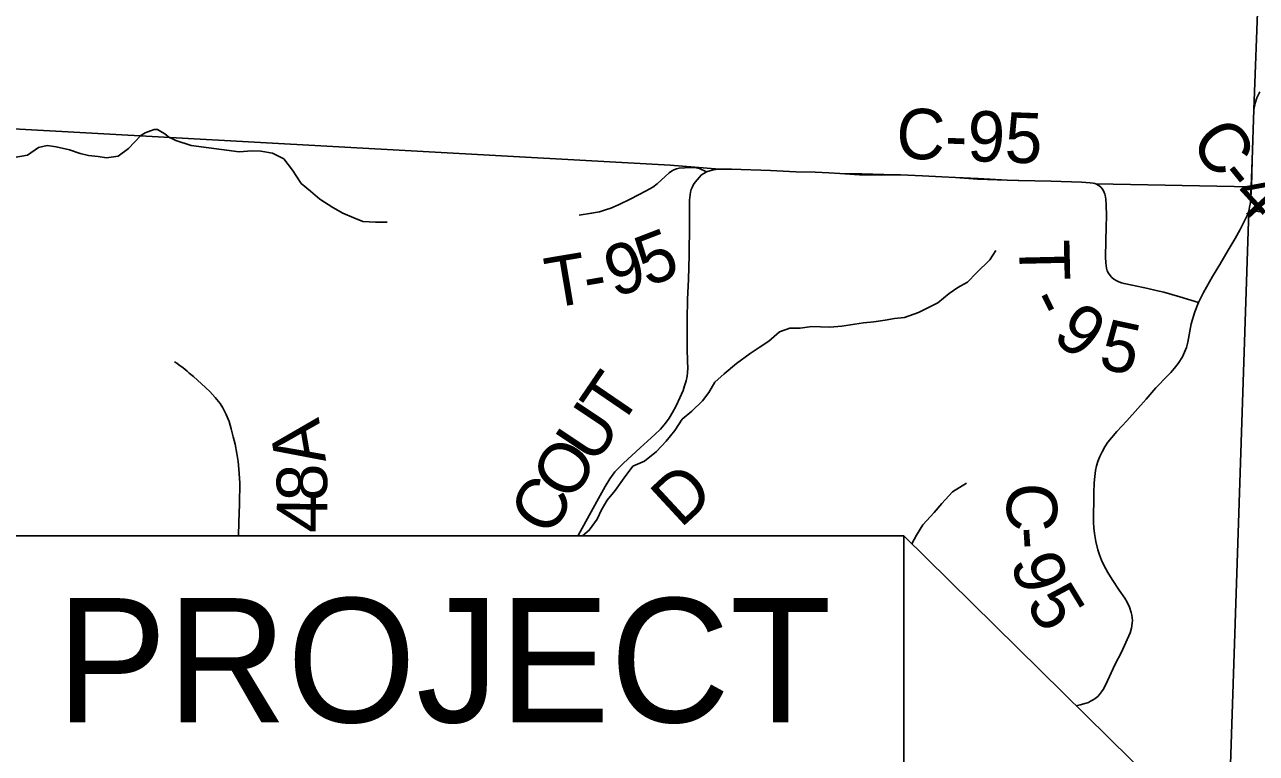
# Model space of a CAD drawing. Extents: x 0 to 34, y 0 to 22.
# Drawn here: x 24.872 to 26.261, y 17.319 to 18.14 of the extents above; entities that cross this region are included whole.
import ezdxf

# ---------------------------------------------------------------- set-up
doc = ezdxf.new("R2010")
doc.units = 0
for name, color, linetype in [('GM_X_Adjacent_County', 7, 'Continuous'), ('GM_X_County', 7, 'Continuous'), ('GM_X_County_Road', 7, 'Continuous'), ('GM_X_County_Road_Text', 7, 'Continuous'), ('GM_X_Minor_River', 7, 'Continuous'), ('GM_X_Township', 7, 'Continuous'), ('GM_X_Township_Road', 7, 'Continuous'), ('GM_X_Township_Road_Text', 7, 'Continuous'), ('SH_Text', 7, 'Continuous')]:
    doc.layers.add(name, color=color, linetype=linetype)

msp = doc.modelspace()

# ---------------------------------------------------------------- linework, layer by layer
at = {"layer": 'GM_X_Adjacent_County'}
for points in [[(26.3979, 17.9244), (26.2521, 17.9299), (26.2531, 17.9341), (26.254, 17.9396), (26.2553, 17.9572), (26.0796, 17.9606), (26.0785, 17.961), (26.0767, 17.9614), (26.0733, 17.9618), (26.0637, 17.9623), (26.0295, 17.9634), (26.0109, 17.964), (25.9929, 17.9644), (25.9923, 17.9644), (25.9799, 17.9648), (25.947, 17.9664), (25.9215, 17.9676), (25.906, 17.9685), (25.8843, 17.9696), (25.8594, 17.9705), (25.8408, 17.971), (25.816, 17.9716), (25.7912, 17.9723), (25.7788, 17.9729), (25.7632, 17.9735), (25.7416, 17.9742), (25.713, 17.9754), (25.6692, 17.9772), (25.6557, 17.9772), (25.5999, 17.9814), (24.5675, 18.0386)], [(24.5675, 18.0386), (25.5999, 17.9814), (25.6557, 17.9772), (25.6692, 17.9772), (25.713, 17.9754), (25.7416, 17.9742), (25.7632, 17.9735), (25.7788, 17.9729), (25.7912, 17.9723), (25.816, 17.9716), (25.8408, 17.971), (25.8594, 17.9705), (25.8843, 17.9696), (25.906, 17.9685), (25.9215, 17.9676), (25.947, 17.9664), (25.9799, 17.9648), (25.9923, 17.9644), (25.9929, 17.9644), (26.0109, 17.964), (26.0295, 17.9634), (26.0637, 17.9623), (26.0733, 17.9618), (26.0767, 17.9614), (26.0785, 17.961), (26.0796, 17.9606), (26.2553, 17.9572), (26.254, 17.9396), (26.2531, 17.9341), (26.2521, 17.9299), (26.3979, 17.9244)]]:
    msp.add_lwpolyline(points, dxfattribs=at)
at = {"layer": 'GM_X_County'}
for points in [[(24.5675, 18.0386), (25.5999, 17.9814), (25.6557, 17.9772), (25.6692, 17.9772), (25.713, 17.9754), (25.7416, 17.9742), (25.7632, 17.9735), (25.7788, 17.9729), (25.7912, 17.9723), (25.816, 17.9716), (25.8408, 17.971), (25.8594, 17.9705), (25.8843, 17.9696), (25.906, 17.9685), (25.9215, 17.9676), (25.947, 17.9664), (25.9799, 17.9648), (25.9923, 17.9644), (25.9929, 17.9644), (26.0109, 17.964), (26.0295, 17.9634), (26.0637, 17.9623), (26.0733, 17.9618), (26.0767, 17.9614), (26.0785, 17.961), (26.0796, 17.9606), (26.2553, 17.9572), (26.254, 17.9396), (26.2531, 17.9341), (26.2521, 17.9299), (26.3979, 17.9244)], [(26.3979, 17.9244), (26.2521, 17.9299), (26.2531, 17.9341), (26.254, 17.9396), (26.2553, 17.9572), (26.0796, 17.9606), (26.0785, 17.961), (26.0767, 17.9614), (26.0733, 17.9618), (26.0637, 17.9623), (26.0295, 17.9634), (26.0109, 17.964), (25.9929, 17.9644), (25.9923, 17.9644), (25.9799, 17.9648), (25.947, 17.9664), (25.9215, 17.9676), (25.906, 17.9685), (25.8843, 17.9696), (25.8594, 17.9705), (25.8408, 17.971), (25.816, 17.9716), (25.7912, 17.9723), (25.7788, 17.9729), (25.7632, 17.9735), (25.7416, 17.9742), (25.713, 17.9754), (25.6692, 17.9772), (25.6557, 17.9772), (25.5999, 17.9814), (24.5675, 18.0386)]]:
    msp.add_lwpolyline(points, dxfattribs=at)
at = {"layer": 'GM_X_County_Road'}
for points in [[(26.2547, 17.9571), (26.2561, 17.9871), (26.2579, 18.0444), (26.2593, 18.0513), (26.2611, 18.0574), (26.2645, 18.0641)], [(25.4958, 17.5637), (25.4966, 17.5651), (25.5191, 17.6059), (25.5268, 17.6195), (25.5319, 17.6282), (25.5375, 17.6358), (25.5473, 17.6459), (25.5662, 17.6631), (25.5825, 17.6782), (25.589, 17.6842), (25.5948, 17.6908), (25.5987, 17.6964), (25.6027, 17.7029), (25.6067, 17.7102), (25.6107, 17.7194), (25.6144, 17.7277), (25.6162, 17.7328), (25.618, 17.7387), (25.6192, 17.7439), (25.6196, 17.7475), (25.6198, 17.7532), (25.6196, 17.7603), (25.619, 17.7751), (25.6189, 17.7888), (25.619, 17.8074), (25.6196, 17.8304), (25.6204, 17.8528), (25.6212, 17.8801), (25.6216, 17.9142), (25.6216, 17.9297), (25.6217, 17.9421), (25.6223, 17.9483), (25.6229, 17.9513), (25.6237, 17.9543), (25.6249, 17.9571), (25.6264, 17.9598), (25.6281, 17.9624), (25.6326, 17.9678), (25.6352, 17.9705), (25.6377, 17.9722), (25.6408, 17.9739)], [(26.0796, 17.9606), (26.0785, 17.961), (26.0767, 17.9614), (26.0733, 17.9618), (26.0637, 17.9623), (26.0295, 17.9634), (26.0109, 17.964), (25.9929, 17.9644), (25.9923, 17.9644), (25.9799, 17.9648), (25.9465, 17.9657), (25.9215, 17.9676), (25.906, 17.9685), (25.8843, 17.9696), (25.8594, 17.9705), (25.838, 17.9702), (25.8132, 17.9705), (25.7912, 17.9723), (25.7788, 17.9729), (25.7632, 17.9735), (25.7416, 17.9742), (25.713, 17.9754), (25.6692, 17.9772), (25.6557, 17.9772)], [(26.2521, 17.9299), (26.2531, 17.9341), (26.254, 17.9396), (26.2541, 17.9426), (26.2547, 17.9571)], [(26.0575, 17.3724), (26.0622, 17.3733), (26.0689, 17.3753), (26.0716, 17.3762), (26.0738, 17.3774), (26.0767, 17.3792), (26.0791, 17.3806), (26.0818, 17.3827), (26.0838, 17.3851), (26.0862, 17.3879), (26.0881, 17.3907), (26.0906, 17.3955), (26.1015, 17.4192), (26.1086, 17.4329), (26.1183, 17.4545), (26.1199, 17.46), (26.1208, 17.4655), (26.1209, 17.4686), (26.1207, 17.4716), (26.1202, 17.4746), (26.1195, 17.4776), (26.1175, 17.4834), (26.115, 17.4891), (26.1125, 17.4936), (26.1062, 17.5026), (26.0981, 17.5146), (26.0931, 17.5226), (26.0887, 17.5308), (26.086, 17.5365), (26.0837, 17.5423), (26.0818, 17.5482), (26.0796, 17.5573), (26.0781, 17.5666), (26.0775, 17.5728), (26.0772, 17.579), (26.0775, 17.6122), (26.078, 17.6237), (26.0785, 17.6306), (26.0793, 17.6375), (26.0804, 17.6426), (26.0819, 17.6475), (26.0843, 17.6531), (26.0867, 17.6585), (26.09, 17.6643), (26.0934, 17.6695), (26.0972, 17.6744), (26.1035, 17.6816), (26.1146, 17.6936), (26.1364, 17.7179), (26.1473, 17.7305), (26.161, 17.7446), (26.1643, 17.7481), (26.168, 17.7526), (26.1725, 17.758), (26.1774, 17.7657), (26.1808, 17.7734), (26.1819, 17.7762), (26.1835, 17.7821), (26.187, 17.8029), (26.1913, 17.8163), (26.1953, 17.8269)]]:
    msp.add_lwpolyline(points, dxfattribs=at)
at = {"layer": 'GM_X_Minor_River'}
for points in [[(24.9961, 18.0075), (25.0034, 18.0151), (25.0083, 18.0181), (25.014, 18.0204), (25.0182, 18.0216), (25.022, 18.0216), (25.0258, 18.0193), (25.0303, 18.0167), (25.0349, 18.0132), (25.039, 18.0114), (25.0428, 18.0095), (25.0601, 18.0038)], [(24.8603, 17.9902), (24.8755, 17.9929), (24.8879, 18.0013), (24.8978, 18.0036), (24.908, 18.0021), (24.9228, 17.9988), (24.9349, 17.9946), (24.9444, 17.9924), (24.955, 17.9913), (24.9644, 17.9898), (24.9777, 17.9917), (24.9892, 18.0004), (24.9961, 18.0075)], [(25.0601, 18.0038), (25.114, 17.9964), (25.1283, 17.9976), (25.1386, 17.9972), (25.1518, 17.995), (25.1643, 17.9886), (25.1742, 17.9761), (25.1841, 17.9609), (25.1944, 17.9523), (25.205, 17.9432), (25.2198, 17.9338), (25.2308, 17.9273), (25.2434, 17.9221), (25.2536, 17.9179), (25.2676, 17.9172), (25.2809, 17.9173)], [(25.5954, 17.6706), (25.6052, 17.6824), (25.6134, 17.6953), (25.6244, 17.7045), (25.6364, 17.7159), (25.6436, 17.7254), (25.6504, 17.7372), (25.6609, 17.7463), (25.6745, 17.7581), (25.69, 17.7692), (25.7002, 17.776), (25.7111, 17.7833), (25.7232, 17.7939), (25.7349, 17.7978), (25.7466, 17.7978), (25.7595, 17.7998), (25.7693, 17.7994), (25.7799, 17.7991), (25.7936, 17.8003), (25.8079, 17.8022), (25.8178, 17.8038), (25.8295, 17.8049), (25.8424, 17.8069), (25.8529, 17.8088), (25.8639, 17.81), (25.8798, 17.8157), (25.9017, 17.8264), (25.9145, 17.8371), (25.9243, 17.8436), (25.9349, 17.8497), (25.9451, 17.8603), (25.9602, 17.8748), (25.9669, 17.8854)], [(25.501, 17.5637), (25.5087, 17.5701), (25.5178, 17.5827), (25.5226, 17.593), (25.529, 17.604), (25.5381, 17.615), (25.5482, 17.6291), (25.558, 17.6424), (25.5709, 17.6481), (25.5844, 17.6588), (25.5954, 17.6706)], [(25.8723, 17.5547), (25.8775, 17.5646), (25.8846, 17.5764), (25.8974, 17.5901), (25.9061, 17.6003), (25.9181, 17.6133), (25.934, 17.6232)]]:
    msp.add_lwpolyline(points, dxfattribs=at)
at = {"layer": 'GM_X_Township'}
for points in [[(24.5675, 18.0386), (25.5999, 17.9814), (25.6557, 17.9772), (25.6692, 17.9772), (25.713, 17.9754), (25.7416, 17.9742), (25.7632, 17.9735), (25.7788, 17.9729), (25.7912, 17.9723), (25.816, 17.9716), (25.8408, 17.971), (25.8594, 17.9705), (25.8843, 17.9696), (25.906, 17.9685), (25.9215, 17.9676), (25.947, 17.9664), (25.9799, 17.9648), (25.9923, 17.9644), (25.9929, 17.9644), (26.0109, 17.964), (26.0295, 17.9634), (26.0637, 17.9623), (26.0733, 17.9618), (26.0767, 17.9614), (26.0785, 17.961), (26.0796, 17.9606), (26.2553, 17.9572), (26.2561, 17.9871), (26.2579, 18.0444), (26.2775, 18.5614)], [(26.2775, 18.5614), (26.2579, 18.0444), (26.2561, 17.9871), (26.2553, 17.9572), (26.254, 17.9396), (26.2531, 17.9341), (26.2521, 17.9299), (26.3979, 17.9244)], [(26.228, 17.2045), (26.2521, 17.9299), (26.2531, 17.9341), (26.254, 17.9396), (26.2553, 17.9572), (26.0796, 17.9606), (26.0785, 17.961), (26.0767, 17.9614), (26.0733, 17.9618), (26.0637, 17.9623), (26.0295, 17.9634), (26.0109, 17.964), (25.9929, 17.9644), (25.9923, 17.9644), (25.9799, 17.9648), (25.947, 17.9664), (25.9215, 17.9676), (25.906, 17.9685), (25.8843, 17.9696), (25.8594, 17.9705), (25.8408, 17.971), (25.816, 17.9716), (25.7912, 17.9723), (25.7788, 17.9729), (25.7632, 17.9735), (25.7416, 17.9742), (25.713, 17.9754), (25.6692, 17.9772), (25.6557, 17.9772), (25.5999, 17.9814), (24.5675, 18.0386)], [(30.8167, 17.8174), (30.1304, 17.8301), (29.8296, 17.8449), (29.1279, 17.8574), (28.6324, 17.8677), (28.1264, 17.8728), (27.8903, 17.8826), (27.7531, 17.8783), (27.1422, 17.8906), (26.9072, 17.9017), (26.4988, 17.9198), (26.3979, 17.9244), (26.2521, 17.9299), (26.228, 17.2045)]]:
    msp.add_lwpolyline(points, dxfattribs=at)
at = {"layer": 'GM_X_Township_Road'}
for points in [[(25.6408, 17.9739), (25.6329, 17.9778), (25.6293, 17.9785), (25.6225, 17.9789), (25.6163, 17.9787), (25.6101, 17.978), (25.6071, 17.9774), (25.6042, 17.9763), (25.6014, 17.9749), (25.5989, 17.973), (25.5943, 17.9689), (25.5899, 17.9645), (25.5852, 17.9604), (25.5802, 17.9568), (25.5722, 17.9521), (25.5555, 17.9435), (25.5418, 17.9369), (25.5329, 17.9332), (25.5271, 17.9312), (25.5203, 17.9291), (25.5114, 17.9274), (25.4974, 17.9251)], [(25.6514, 17.9767), (25.6483, 17.9763), (25.6408, 17.9739)], [(26.0805, 17.9601), (26.0796, 17.9606), (26.0785, 17.961), (26.0767, 17.9614), (26.0733, 17.9618), (26.0637, 17.9623), (26.0295, 17.9634), (26.0109, 17.964), (25.9929, 17.9644), (25.9923, 17.9644), (25.9799, 17.9648), (25.947, 17.9664), (25.9215, 17.9676), (25.906, 17.9685), (25.8843, 17.9696), (25.8594, 17.9705), (25.8408, 17.971), (25.816, 17.9716), (25.7912, 17.9723), (25.7788, 17.9729), (25.7632, 17.9735), (25.7416, 17.9742), (25.713, 17.9754), (25.6692, 17.9772), (25.6557, 17.9772), (25.6514, 17.9767)], [(26.1953, 17.8269), (26.1744, 17.8331), (26.1565, 17.8383), (26.1476, 17.8405), (26.1385, 17.8425), (26.1205, 17.8462), (26.1115, 17.8482), (26.1085, 17.8491), (26.1056, 17.8501), (26.1028, 17.8514), (26.1001, 17.853), (26.0977, 17.855), (26.0957, 17.8572), (26.094, 17.8598), (26.0926, 17.8625), (26.0917, 17.8655), (26.0912, 17.8685), (26.0909, 17.8716), (26.0907, 17.8778), (26.0911, 17.8964), (26.0912, 17.9118), (26.0916, 17.9243), (26.0915, 17.9367), (26.0911, 17.9429), (26.0907, 17.9459), (26.0899, 17.9489), (26.0888, 17.9517), (26.0872, 17.9544), (26.0852, 17.9567), (26.0831, 17.9585), (26.0816, 17.9595), (26.0805, 17.9601)], [(26.2521, 17.9299), (26.2531, 17.9341), (26.254, 17.9396), (26.2547, 17.9571)], [(26.1953, 17.8269), (26.2012, 17.8379), (26.2113, 17.856), (26.2196, 17.8695), (26.2289, 17.8856), (26.2366, 17.8991), (26.2423, 17.9092), (26.2513, 17.9271), (26.2521, 17.9299)], [(25.1134, 17.5637), (25.1138, 17.5791), (25.1144, 17.5995), (25.1147, 17.6235), (25.1139, 17.639), (25.113, 17.6476), (25.1116, 17.6567), (25.1094, 17.6673), (25.1074, 17.6753), (25.1052, 17.6844), (25.1027, 17.6926), (25.0995, 17.7006), (25.0956, 17.7081), (25.0925, 17.7128), (25.0871, 17.7197), (25.081, 17.7266), (25.0717, 17.7352), (25.0672, 17.7394), (25.0626, 17.7435), (25.0579, 17.7473), (25.0556, 17.7493), (25.0532, 17.7512), (25.0509, 17.7531), (25.0462, 17.7567), (25.0438, 17.7584), (25.0412, 17.76)]]:
    msp.add_lwpolyline(points, dxfattribs=at)
at = {"layer": 'SH_Text'}
for points in [[(24.3906, 17.0737), (25.8632, 17.0737), (25.8632, 17.5637), (24.3906, 17.5637)], [(26.7096, 16.7303), (25.8632, 17.0737), (25.8632, 17.5637)]]:
    msp.add_lwpolyline(points, close=True, dxfattribs=at)

# ---------------------------------------------------------------- texts
at = {"layer": 'GM_X_County_Road_Text'}
for s, height, rotation, p in [('C-95', 0.05682, 357.8758, (25.854, 17.9893)), ('C', 0.0568, 305.7169, (26.1845, 18.008)), ('-', 0.0568, 308.9827, (26.2139, 17.9673)), ('4', 0.0568, 312.5205, (26.2311, 17.9463)), ('T', 0.0568, 55.7204, (25.5427, 17.6839)), ('U', 0.0568, 56.317, (25.515, 17.6425)), ('O', 0.0568, 57.7548, (25.4886, 17.6005)), ('D', 0.0568, 42.8307, (25.6117, 17.5716)), ('C', 0.0568, 58.5242, (25.4643, 17.5609)), ('C', 0.0568, 269.3521, (25.9797, 17.6239)), ('-', 0.0568, 273.8029, (25.9793, 17.5724)), ('9', 0.0568, 286.7614, (25.9833, 17.5354)), ('5', 0.0568, 301.2278, (25.9998, 17.4876))]:
    msp.add_text(s, height=height, rotation=rotation, dxfattribs=at).set_placement(p)
at = {"layer": 'GM_X_Township_Road_Text'}
for s, rotation, p in [('5', 21.0274, (25.5743, 17.8439)), ('T', 271.3158, (25.9931, 17.897)), ('T', 9.5689, (25.4645, 17.82)), ('9', 16.2544, (25.5361, 17.8326)), ('-', 9.7923, (25.5065, 17.8271)), ('-', 296.179, (26.0004, 17.8286)), ('9', 322.7739, (26.0288, 17.7856)), ('5', 347.9037, (26.0812, 17.7532)), ('A', 99.7831, (25.2122, 17.6482)), ('8', 90.4826, (25.2134, 17.6032)), ('4', 89.3392, (25.213, 17.5669))]:
    msp.add_text(s, height=0.0568, rotation=rotation, dxfattribs=at).set_placement(p)
at = {"layer": 'SH_Text'}
msp.add_text('END PROJECT', height=0.14, dxfattribs=at).set_placement((24.4606, 17.3537))

doc.saveas('drawing.dxf')
